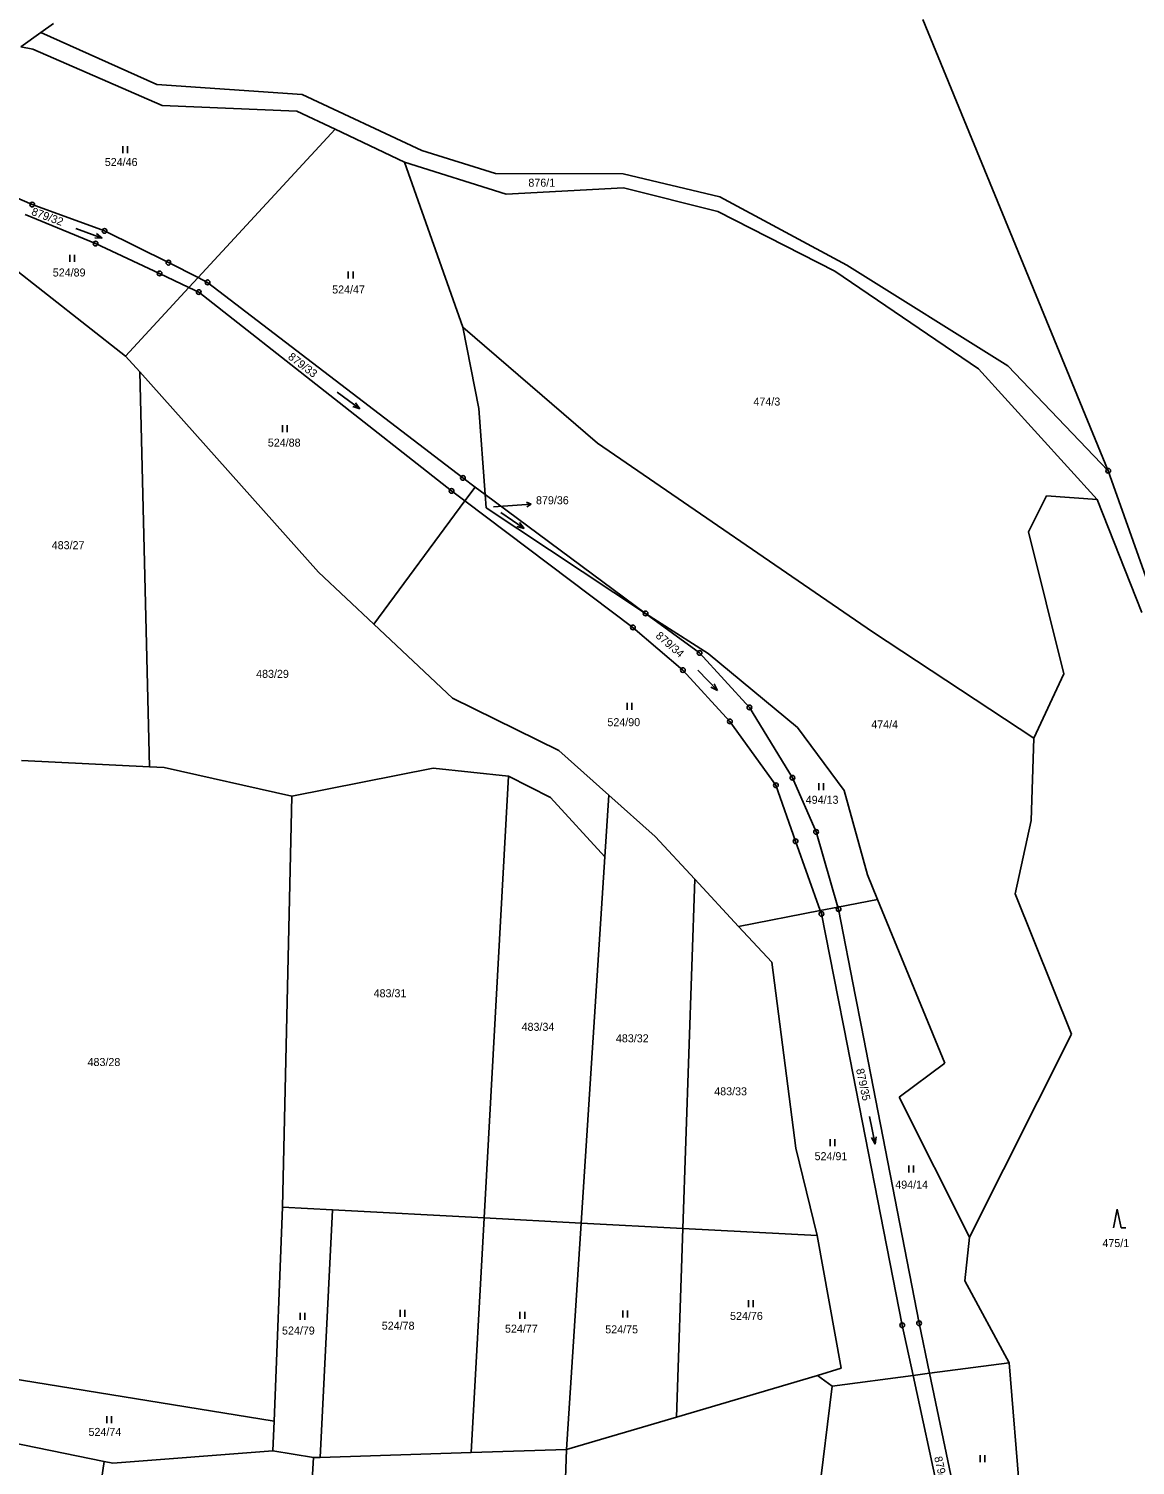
# Model space of a CAD drawing. Extents: x -791032 to -787751, y -1106872 to -1104403.
# Drawn here: x -788244.6 to -788009.7, y -1105392.2 to -1105087.2 of the extents above; entities that cross this region are included whole.
import ezdxf

# ---------------------------------------------------------------- set-up
doc = ezdxf.new("R2010")
doc.units = 0
for name, color, linetype in [('Komunikace', 7, 'Continuous'), ('Vrstva 1', 7, 'Continuous'), ('Vrstva 14', 7, 'Continuous'), ('Vrstva 16', 7, 'Continuous'), ('Vrstva 23', 7, 'Continuous'), ('Vrstva 28', 7, 'Continuous'), ('Vrstva 4', 7, 'Continuous')]:
    doc.layers.add(name, color=color, linetype=linetype)

msp = doc.modelspace()

# ---------------------------------------------------------------- linework, layer by layer
at = {"layer": 'Komunikace'}
msp.add_line((-788145.98, -1105188.69), (-788140.92, -1105188.35), dxfattribs=at)
at = {"layer": 'Vrstva 1'}
for p, q in [((-788246.28, -1105091.03), (-788242.04, -1105087.95)), ((-788242.04, -1105087.95), (-788239.38, -1105086.02)), ((-788242.04, -1105087.95), (-788217.42, -1105098.97)), ((-788246.28, -1105091.03), (-788243.75, -1105091.5)), ((-788243.75, -1105091.5), (-788216.34, -1105103.48)), ((-788217.42, -1105098.97), (-788186.56, -1105101.16)), ((-788186.56, -1105101.16), (-788161.2, -1105113.03)), ((-788216.34, -1105103.48), (-788187.72, -1105104.65)), ((-788187.72, -1105104.65), (-788179.59, -1105108.5)), ((-788179.59, -1105108.5), (-788208.69, -1105140)), ((-788179.59, -1105108.5), (-788164.83, -1105115.5)), ((-788243.9, -1105124.5), (-788266.65, -1105114.67)), ((-788161.2, -1105113.03), (-788145.52, -1105117.92)), ((-788164.83, -1105115.5), (-788143.23, -1105122.27)), ((-788152.45, -1105150.55), (-788164.83, -1105115.5)), ((-788145.52, -1105117.92), (-788118.39, -1105118.01)), ((-788118.39, -1105118.01), (-788097.9, -1105122.86)), ((-788143.23, -1105122.27), (-788118.34, -1105120.97)), ((-788118.34, -1105120.97), (-788098.35, -1105126.01)), ((-788228.53, -1105130.09), (-788243.9, -1105124.5)), ((-788097.9, -1105122.86), (-788070.94, -1105137.39)), ((-788230.44, -1105132.78), (-788245.37, -1105126.64)), ((-788098.35, -1105126.01), (-788073.48, -1105138.68)), ((-788214.97, -1105136.84), (-788228.53, -1105130.09)), ((-788216.85, -1105139.14), (-788230.44, -1105132.78)), ((-788208.69, -1105140), (-788214.97, -1105136.84)), ((-788224.09, -1105156.67), (-788248.95, -1105137.17)), ((-788210.62, -1105142.09), (-788216.85, -1105139.14)), ((-788073.48, -1105138.68), (-788043, -1105159.39)), ((-788070.94, -1105137.39), (-788036.72, -1105158.76)), ((-788210.62, -1105142.09), (-788224.09, -1105156.67)), ((-788208.69, -1105140), (-788210.62, -1105142.09)), ((-788208.54, -1105143.08), (-788210.62, -1105142.09)), ((-788206.66, -1105141.02), (-788208.69, -1105140)), ((-788152.44, -1105182.55), (-788206.66, -1105141.02)), ((-788154.86, -1105185.31), (-788208.54, -1105143.08)), ((-788152.45, -1105150.55), (-788123.85, -1105175.21)), ((-788149.05, -1105167.82), (-788152.45, -1105150.55)), ((-788221.07, -1105160.05), (-788224.09, -1105156.67)), ((-788218.99, -1105243.92), (-788221.07, -1105160.05)), ((-788183.13, -1105202.55), (-788221.07, -1105160.05)), ((-788043, -1105159.39), (-788017.77, -1105187.16)), ((-788036.72, -1105158.76), (-788015.44, -1105181.04)), ((-788147.72, -1105186.05), (-788149.05, -1105167.82)), ((-788123.85, -1105175.21), (-788065.5, -1105215.21)), ((-788149.82, -1105184.49), (-788152.44, -1105182.55)), ((-788152.01, -1105187.45), (-788154.86, -1105185.31)), ((-788152.01, -1105187.45), (-788149.82, -1105184.49)), ((-788147.72, -1105186.05), (-788149.82, -1105184.49)), ((-788171.39, -1105213.59), (-788152.01, -1105187.45)), ((-788116.35, -1105214.3), (-788152.01, -1105187.45)), ((-788147.72, -1105186.05), (-788147.51, -1105188.9)), ((-788113.66, -1105211.34), (-788147.72, -1105186.05)), ((-788032.33, -1105194.04), (-788028.51, -1105186.35)), ((-788028.51, -1105186.35), (-788017.77, -1105187.16)), ((-788017.77, -1105187.16), (-788008.3, -1105211.16)), ((-788113.66, -1105211.34), (-788147.51, -1105188.9)), ((-788024.87, -1105224.16), (-788032.33, -1105194.04)), ((-788171.39, -1105213.59), (-788183.13, -1105202.55)), ((-788102.19, -1105219.71), (-788113.66, -1105211.34)), ((-788113.66, -1105211.34), (-788100.36, -1105219.86)), ((-788154.64, -1105229.33), (-788171.39, -1105213.59)), ((-788105.74, -1105223.36), (-788116.35, -1105214.3)), ((-788065.5, -1105215.21), (-788031.2, -1105237.84)), ((-788091.6, -1105231.3), (-788102.19, -1105219.71)), ((-788100.36, -1105219.86), (-788081.41, -1105235.59)), ((-788095.75, -1105234.28), (-788105.74, -1105223.36)), ((-788031.2, -1105237.84), (-788024.87, -1105224.16)), ((-788132.05, -1105240.47), (-788154.64, -1105229.33)), ((-788082.49, -1105246.24), (-788091.6, -1105231.3)), ((-788085.99, -1105247.83), (-788095.75, -1105234.28)), ((-788081.41, -1105235.59), (-788071.52, -1105248.92)), ((-788121.45, -1105249.93), (-788132.05, -1105240.47)), ((-788031.79, -1105255.34), (-788031.2, -1105237.84)), ((-788246.2, -1105242.57), (-788218.99, -1105243.92)), ((-788218.99, -1105243.92), (-788215.85, -1105244.07)), ((-788215.85, -1105244.07), (-788188.79, -1105250.12)), ((-788188.79, -1105250.12), (-788158.73, -1105244.18)), ((-788158.73, -1105244.18), (-788142.79, -1105245.91)), ((-788142.79, -1105245.91), (-788147.94, -1105339.71)), ((-788142.79, -1105245.91), (-788133.87, -1105250.4)), ((-788077.46, -1105257.74), (-788082.49, -1105246.24)), ((-788081.82, -1105259.73), (-788085.99, -1105247.83)), ((-788071.52, -1105248.92), (-788066.55, -1105266.85)), ((-788190.76, -1105337.44), (-788188.79, -1105250.12)), ((-788122.3, -1105263.02), (-788133.87, -1105250.4)), ((-788121.45, -1105249.93), (-788122.3, -1105263.02)), ((-788111.64, -1105258.69), (-788121.45, -1105249.93)), ((-788035.17, -1105270.89), (-788031.79, -1105255.34)), ((-788103.23, -1105267.75), (-788111.64, -1105258.69)), ((-788072.81, -1105273.7), (-788077.46, -1105257.74)), ((-788076.57, -1105274.43), (-788081.82, -1105259.73)), ((-788122.3, -1105263.02), (-788127.35, -1105340.8)), ((-788105.76, -1105341.95), (-788103.23, -1105267.75)), ((-788093.91, -1105277.8), (-788103.23, -1105267.75)), ((-788066.55, -1105266.85), (-788064.41, -1105272.06)), ((-788023.26, -1105300.69), (-788035.17, -1105270.89)), ((-788076.57, -1105274.43), (-788072.81, -1105273.7)), ((-788072.81, -1105273.7), (-788064.41, -1105272.06)), ((-788072.69, -1105274.11), (-788072.81, -1105273.7)), ((-788072.69, -1105274.11), (-788069.08, -1105292.69)), ((-788064.41, -1105272.06), (-788050.12, -1105306.85)), ((-788093.91, -1105277.8), (-788076.57, -1105274.43)), ((-788076.32, -1105275.14), (-788076.57, -1105274.43)), ((-788076.32, -1105275.14), (-788072.8, -1105293.09)), ((-788086.83, -1105285.43), (-788093.91, -1105277.8)), ((-788081.77, -1105324.87), (-788086.83, -1105285.43)), ((-788072.8, -1105293.09), (-788071.6, -1105299.18)), ((-788069.08, -1105292.69), (-788067.89, -1105298.78)), ((-788059.17, -1105362.52), (-788071.6, -1105299.18)), ((-788055.59, -1105362.09), (-788067.89, -1105298.78)), ((-788044.87, -1105343.83), (-788023.26, -1105300.69)), ((-788050.12, -1105306.85), (-788059.84, -1105314.07)), ((-788059.84, -1105314.07), (-788044.87, -1105343.83)), ((-788077.22, -1105343.46), (-788081.77, -1105324.87)), ((-788192.53, -1105382.87), (-788190.76, -1105337.44)), ((-788190.76, -1105337.44), (-788180.12, -1105338)), ((-788182.79, -1105390.58), (-788180.12, -1105338)), ((-788180.12, -1105338), (-788147.94, -1105339.71)), ((-788150.68, -1105389.56), (-788147.94, -1105339.71)), ((-788147.94, -1105339.71), (-788127.35, -1105340.8)), ((-788127.35, -1105340.8), (-788130.47, -1105388.92)), ((-788127.35, -1105340.8), (-788105.76, -1105341.95)), ((-788107.12, -1105382.01), (-788105.76, -1105341.95)), ((-788105.76, -1105341.95), (-788077.22, -1105343.46)), ((-788072.14, -1105371.65), (-788077.22, -1105343.46)), ((-788045.89, -1105353.09), (-788044.87, -1105343.83)), ((-788036.5, -1105370.49), (-788045.89, -1105353.09)), ((-788056.87, -1105373.18), (-788059.17, -1105362.52)), ((-788053.36, -1105372.72), (-788055.59, -1105362.09)), ((-788077.19, -1105373.15), (-788072.14, -1105371.65)), ((-788036.5, -1105370.49), (-788053.36, -1105372.72)), ((-788033.62, -1105405.42), (-788036.5, -1105370.49)), ((-788254.48, -1105372.85), (-788192.53, -1105382.87)), ((-788107.12, -1105382.01), (-788077.19, -1105373.15)), ((-788077.19, -1105373.15), (-788074.06, -1105375.44)), ((-788056.87, -1105373.18), (-788074.06, -1105375.44)), ((-788053.36, -1105372.72), (-788056.87, -1105373.18)), ((-788045.37, -1105426.5), (-788056.87, -1105373.18)), ((-788042.15, -1105426.09), (-788053.36, -1105372.72)), ((-788074.06, -1105375.44), (-788081.29, -1105434.62)), ((-788192.53, -1105382.87), (-788192.78, -1105389.17)), ((-788130.47, -1105388.92), (-788107.12, -1105382.01)), ((-788252.08, -1105386.66), (-788228.63, -1105391.41)), ((-788226.77, -1105391.79), (-788192.78, -1105389.17)), ((-788192.78, -1105389.17), (-788184.19, -1105390.62)), ((-788182.79, -1105390.58), (-788150.68, -1105389.56)), ((-788150.68, -1105389.56), (-788130.47, -1105388.92)), ((-788130.47, -1105388.92), (-788132.01, -1105433.71)), ((-788228.63, -1105391.41), (-788231.17, -1105408.51)), ((-788228.63, -1105391.41), (-788226.77, -1105391.79)), ((-788184.19, -1105390.62), (-788185.84, -1105419.71)), ((-788184.19, -1105390.62), (-788182.79, -1105390.58))]:
    msp.add_line(p, q, dxfattribs=at)
at = {"layer": 'Vrstva 16'}
for p, q in [((-788140.92, -1105188.35), (-788137.926, -1105188.149)), ((-788137.926, -1105188.149), (-788138.957, -1105187.717)), ((-788137.926, -1105188.149), (-788138.891, -1105188.715))]:
    msp.add_line(p, q, dxfattribs=at)
at = {"layer": 'Vrstva 23'}
for p, q in [((-788224.65, -1105113.62), (-788224.65, -1105112.12)), ((-788223.65, -1105112.12), (-788223.65, -1105113.62)), ((-788234.65, -1105129.566), (-788229.009, -1105131.613)), ((-788229.009, -1105131.613), (-788230.249, -1105130.631)), ((-788229.009, -1105131.613), (-788230.59, -1105131.571)), ((-788235.89, -1105136.69), (-788235.89, -1105135.19)), ((-788234.89, -1105135.19), (-788234.89, -1105136.69)), ((-788176.78, -1105140.22), (-788176.78, -1105138.72)), ((-788175.78, -1105138.72), (-788175.78, -1105140.22)), ((-788179.164, -1105164.353), (-788174.315, -1105167.886)), ((-788174.315, -1105167.886), (-788175.233, -1105166.599)), ((-788174.315, -1105167.886), (-788175.822, -1105167.407)), ((-788190.79, -1105172.83), (-788190.79, -1105171.33)), ((-788189.79, -1105171.33), (-788189.79, -1105172.83)), ((-788144.391, -1105189.909), (-788139.448, -1105193.31)), ((-788139.448, -1105193.31), (-788140.967, -1105192.872)), ((-788139.448, -1105193.31), (-788140.4, -1105192.048)), ((-788102.582, -1105223.419), (-788098.397, -1105227.72)), ((-788098.397, -1105227.72), (-788099.802, -1105226.993)), ((-788098.397, -1105227.72), (-788099.085, -1105226.296)), ((-788117.6, -1105231.79), (-788117.6, -1105230.29)), ((-788116.6, -1105230.29), (-788116.6, -1105231.79)), ((-788076.88, -1105248.86), (-788076.88, -1105247.36)), ((-788075.88, -1105247.36), (-788075.88, -1105248.86)), ((-788066.119, -1105318.162), (-788064.901, -1105324.037)), ((-788064.901, -1105324.037), (-788065.695, -1105322.67)), ((-788064.901, -1105324.037), (-788064.715, -1105322.467)), ((-788074.47, -1105324.46), (-788074.47, -1105322.96)), ((-788073.47, -1105322.96), (-788073.47, -1105324.46)), ((-788057.77, -1105330.08), (-788057.77, -1105328.58)), ((-788056.77, -1105328.58), (-788056.77, -1105330.08)), ((-788014.3, -1105341.82), (-788013.5, -1105337.82)), ((-788013.5, -1105337.82), (-788012.7, -1105341.82)), ((-788012.7, -1105341.82), (-788011.7, -1105341.82)), ((-788165.79, -1105360.75), (-788165.79, -1105359.25)), ((-788164.79, -1105359.25), (-788164.79, -1105360.75)), ((-788118.48, -1105360.86), (-788118.48, -1105359.36)), ((-788117.48, -1105359.36), (-788117.48, -1105360.86)), ((-788091.83, -1105358.68), (-788091.83, -1105357.18)), ((-788090.83, -1105357.18), (-788090.83, -1105358.68)), ((-788187, -1105361.34), (-788187, -1105359.84)), ((-788186, -1105359.84), (-788186, -1105361.34)), ((-788140.33, -1105361.13), (-788140.33, -1105359.63)), ((-788139.33, -1105359.63), (-788139.33, -1105361.13)), ((-788228.07, -1105383.31), (-788228.07, -1105381.81)), ((-788227.07, -1105381.81), (-788227.07, -1105383.31)), ((-788042.64, -1105391.62), (-788042.64, -1105390.12)), ((-788041.64, -1105390.12), (-788041.64, -1105391.62))]:
    msp.add_line(p, q, dxfattribs=at)
at = {"layer": 'Vrstva 28'}
for centre, radius in [((-788243.9, -1105124.5), 0.5), ((-788243.9, -1105124.5), 0.01), ((-788228.53, -1105130.09), 0.5), ((-788228.53, -1105130.09), 0.01), ((-788230.44, -1105132.78), 0.5), ((-788230.44, -1105132.78), 0.01), ((-788214.97, -1105136.84), 0.5), ((-788214.97, -1105136.84), 0.01), ((-788216.85, -1105139.14), 0.5), ((-788216.85, -1105139.14), 0.01), ((-788208.54, -1105143.08), 0.5), ((-788206.66, -1105141.02), 0.5), ((-788206.66, -1105141.02), 0.01), ((-788208.54, -1105143.08), 0.01), ((-788152.44, -1105182.55), 0.5), ((-788152.44, -1105182.55), 0.01), ((-788015.44, -1105181.04), 0.5), ((-788015.44, -1105181.04), 0.01), ((-788154.86, -1105185.31), 0.5), ((-788154.86, -1105185.31), 0.01), ((-788113.66, -1105211.34), 0.5), ((-788113.66, -1105211.34), 0.01), ((-788116.35, -1105214.3), 0.5), ((-788116.35, -1105214.3), 0.01), ((-788102.19, -1105219.71), 0.5), ((-788102.19, -1105219.71), 0.01), ((-788105.74, -1105223.36), 0.5), ((-788105.74, -1105223.36), 0.01), ((-788091.6, -1105231.3), 0.5), ((-788091.6, -1105231.3), 0.01), ((-788095.75, -1105234.28), 0.5), ((-788095.75, -1105234.28), 0.01), ((-788082.49, -1105246.24), 0.5), ((-788082.49, -1105246.24), 0.01), ((-788085.99, -1105247.83), 0.5), ((-788085.99, -1105247.83), 0.01), ((-788077.46, -1105257.74), 0.5), ((-788077.46, -1105257.74), 0.01), ((-788081.82, -1105259.73), 0.5), ((-788081.82, -1105259.73), 0.01), ((-788072.69, -1105274.11), 0.5), ((-788072.69, -1105274.11), 0.01), ((-788076.32, -1105275.14), 0.5), ((-788076.32, -1105275.14), 0.01), ((-788059.17, -1105362.52), 0.5), ((-788059.17, -1105362.52), 0.01), ((-788055.59, -1105362.09), 0.5), ((-788055.59, -1105362.09), 0.01)]:
    msp.add_circle(centre, radius, dxfattribs=at)
at = {"layer": 'Vrstva 4'}
for p, q in [((-788054.8, -1105085.2), (-788015.44, -1105181.04)), ((-788015.44, -1105181.04), (-788005.64, -1105208.73))]:
    msp.add_line(p, q, dxfattribs=at)

# ---------------------------------------------------------------- texts
at = {"layer": 'Vrstva 14'}
for s, height, p in [('524/46', 1.7, (-788228.488, -1105116.32)), ('876/1', 1.7, (-788138.55, -1105120.71)), ('524/89', 1.7, (-788239.532, -1105139.78)), ('524/47', 1.7, (-788180.214, -1105143.39)), ('474/3', 1.7, (-788090.758, -1105167.19)), ('524/88', 1.7, (-788193.871, -1105175.91)), ('879/36', 0.1, (-788146.233, -1105188.69)), ('483/27', 1.7, (-788239.752, -1105197.69)), ('483/29', 1.7, (-788196.355, -1105225.02)), ('524/90', 1.7, (-788121.771, -1105235.28)), ('474/4', 1.7, (-788065.744, -1105235.74)), ('494/13', 1.7, (-788079.665, -1105251.76)), ('483/31', 1.7, (-788171.409, -1105292.85)), ('483/34', 1.7, (-788139.991, -1105299.98)), ('483/32', 1.7, (-788119.965, -1105302.42)), ('483/28', 1.7, (-788232.145, -1105307.46)), ('483/33', 1.7, (-788099.086, -1105313.68)), ('524/91', 1.7, (-788077.775, -1105327.45)), ('494/14', 1.7, (-788060.651, -1105333.49)), ('475/1', 1.7, (-788016.662, -1105345.91)), ('524/78', 1.7, (-788169.678, -1105363.45)), ('524/77', 1.7, (-788143.515, -1105364.08)), ('524/75', 1.7, (-788122.225, -1105364.23)), ('524/76', 1.7, (-788095.728, -1105361.38)), ('524/79', 1.7, (-788190.858, -1105364.48)), ('524/74', 1.7, (-788231.944, -1105386.01))]:
    msp.add_text(s, height=height, dxfattribs=at).set_placement(p)
for s, rotation, p in [('879/32', 339.74703, (-788244.211, -1105126.646)), ('879/33', 322.67124, (-788189.734, -1105157.148)), ('879/34', 319.20264, (-788111.672, -1105216.301)), ('879/35', 281.93166, (-788068.983, -1105308.16)), ('879/26', 282.80088, (-788052.409, -1105390.549))]:
    msp.add_text(s, height=1.7, rotation=rotation, dxfattribs=at).set_placement(p)
at = {"layer": 'Vrstva 16'}
msp.add_text('879/36', height=1.7, dxfattribs=at).set_placement((-788136.93, -1105188.15))

doc.saveas('drawing.dxf')
